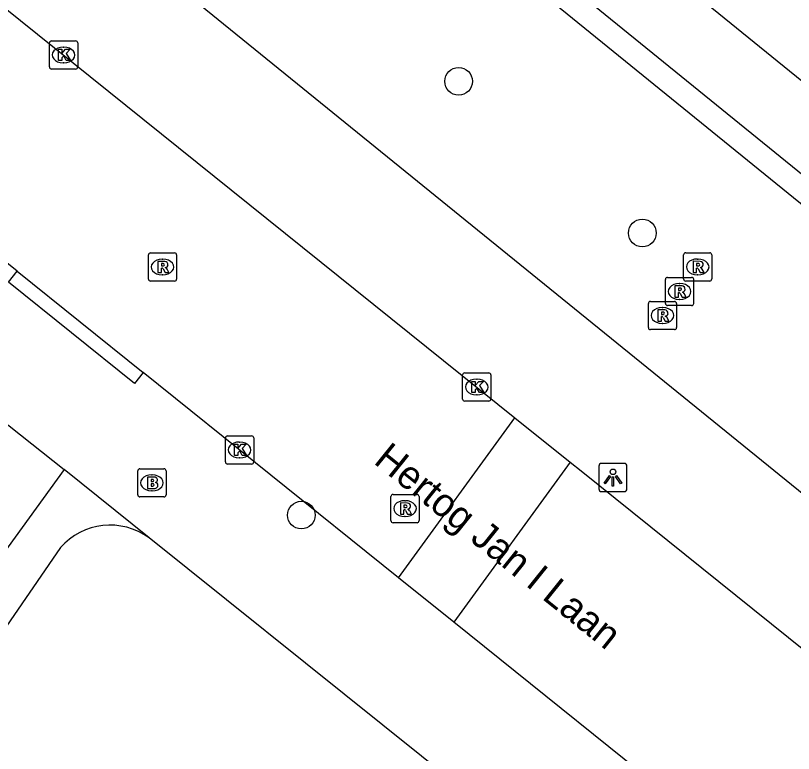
# Model space of a CAD drawing. Extents: x 159675 to 160530, y 382179 to 382901.
# Drawn here: x 160311.53 to 160339.08, y 382679.85 to 382705.99 of the extents above; entities that cross this region are included whole.
import ezdxf

# ---------------------------------------------------------------- set-up
doc = ezdxf.new("R2010")
doc.units = 0
for name, color, linetype in [('IMGEO_Boom', 7, 'Continuous'), ('IMGEO_Brandkraan', 7, 'Continuous'), ('IMGEO_Haag', 7, 'Continuous'), ('IMGEO_Kolk', 7, 'Continuous'), ('IMGEO_Lichtpunt', 7, 'Continuous'), ('IMGEO_Openbare_ruimte_label', 7, 'Continuous'), ('IMGEO_Pand', 7, 'Continuous'), ('IMGEO_Rijbaan_lokaal_open', 7, 'Continuous'), ('IMGEO_Rioolput', 7, 'Continuous'), ('IMGEO_Voetpad_open', 7, 'Continuous')]:
    doc.layers.add(name, color=color, linetype=linetype)

msp = doc.modelspace()

# ---------------------------------------------------------------- linework, layer by layer
at = {"layer": 'IMGEO_Boom'}
for centre in [(160327.217, 382703.665), (160333.725, 382698.29), (160321.648, 382688.295)]:
    msp.add_circle(centre, 0.489, dxfattribs=at)
at = {"layer": 'IMGEO_Brandkraan'}
for p, q in [((160315.853, 382689.013), (160315.853, 382689.865)), ((160315.928, 382689.939), (160316.78, 382689.939)), ((160316.341, 382689.719), (160316.366, 382689.719)), ((160316.854, 382689.865), (160316.854, 382689.013)), ((160316.78, 382688.939), (160315.928, 382688.939)), ((160316.364, 382689.159), (160316.339, 382689.159))]:
    msp.add_line(p, q, dxfattribs=at)
for points in [[(160315.853, 382689.013), (160315.853, 382689.865)], [(160315.928, 382689.939), (160316.78, 382689.939)], [(160316.854, 382689.865), (160316.854, 382689.013)], [(160316.201, 382689.639), (160316.201, 382689.239), (160316.414, 382689.239)], [(160316.432, 382689.639), (160316.201, 382689.639)], [(160316.38, 382689.558), (160316.326, 382689.558), (160316.326, 382689.482)], [(160316.326, 382689.482), (160316.379, 382689.482)], [(160316.388, 382689.406), (160316.326, 382689.406), (160316.326, 382689.325)], [(160316.326, 382689.325), (160316.388, 382689.325)], [(160316.78, 382688.939), (160315.928, 382688.939)]]:
    msp.add_lwpolyline(points, dxfattribs=at)
for centre, radius, start, end in [((160315.93, 382689.863), 0.0765, 91.552, 178.448), ((160315.93, 382689.863), 0.0765, 91.552, 178.448), ((160316.778, 382689.863), 0.0765, 1.552, 88.448), ((160316.778, 382689.863), 0.0765, 1.552, 88.448), ((160316.381, 382689.52), 0.0379, 267.8285, 90.9355), ((160316.436, 382689.494), 0.145, 59.4692, 91.5367), ((160316.461, 382689.541), 0.0922, 285.5137, 58.1501), ((160316.466, 382689.349), 0.105, 301.3115, 78.989), ((160316.389, 382689.365), 0.0404, 269.8759, 90.5077), ((160316.42, 382689.49), 0.251, 268.6676, 293.5347), ((160315.93, 382689.015), 0.0765, 181.552, 268.448), ((160315.93, 382689.015), 0.0765, 181.552, 268.448), ((160316.778, 382689.015), 0.0765, 271.552, 358.448), ((160316.778, 382689.015), 0.0765, 271.552, 358.448)]:
    msp.add_arc(centre, radius, start, end, dxfattribs=at)
for centre, major_axis, ratio, start_param, end_param in [((160316.34, 382689.439), (-0.387, 0.002), 0.722429, 4.712389, 7.853982), ((160316.365, 382689.439), (-0.39, 0.002), 0.717154, 1.570796, 4.712389)]:
    msp.add_ellipse(centre, major_axis=major_axis, ratio=ratio, start_param=start_param, end_param=end_param, dxfattribs=at)
at = {"layer": 'IMGEO_Haag'}
msp.add_lwpolyline([(160362, 382680.937), (160317.229, 382717.291), (160317.757, 382717.941)], dxfattribs=at)
at = {"layer": 'IMGEO_Kolk'}
for p, q in [((160312.724, 382704.172), (160312.724, 382705.024)), ((160312.799, 382705.098), (160313.651, 382705.098)), ((160313.212, 382704.878), (160313.237, 382704.878)), ((160313.725, 382705.024), (160313.725, 382704.172)), ((160313.651, 382704.098), (160312.799, 382704.098)), ((160313.235, 382704.318), (160313.21, 382704.318)), ((160327.436, 382693.334), (160328.288, 382693.334)), ((160327.361, 382692.408), (160327.361, 382693.26)), ((160327.849, 382693.114), (160327.874, 382693.114)), ((160328.362, 382693.26), (160328.362, 382692.408)), ((160327.872, 382692.554), (160327.847, 382692.554)), ((160328.288, 382692.334), (160327.436, 382692.334)), ((160319.034, 382691.104), (160319.886, 382691.104)), ((160318.959, 382690.178), (160318.959, 382691.03)), ((160319.447, 382690.884), (160319.472, 382690.884)), ((160319.96, 382691.03), (160319.96, 382690.178)), ((160319.47, 382690.324), (160319.445, 382690.324)), ((160319.886, 382690.104), (160319.034, 382690.104))]:
    msp.add_line(p, q, dxfattribs=at)
for points in [[(160312.724, 382704.172), (160312.724, 382705.024)], [(160312.799, 382705.098), (160313.651, 382705.098)], [(160313.725, 382705.024), (160313.725, 382704.172)], [(160313.045, 382704.798), (160313.168, 382704.798), (160313.168, 382704.647), (160313.298, 382704.798), (160313.462, 382704.798), (160313.316, 382704.647), (160313.469, 382704.398), (160313.317, 382704.398), (160313.232, 382704.562), (160313.168, 382704.495), (160313.168, 382704.398), (160313.045, 382704.398), (160313.045, 382704.798)], [(160313.651, 382704.098), (160312.799, 382704.098)], [(160327.436, 382693.334), (160328.288, 382693.334)], [(160327.361, 382692.408), (160327.361, 382693.26)], [(160327.682, 382693.034), (160327.805, 382693.034), (160327.805, 382692.883), (160327.935, 382693.034), (160328.099, 382693.034), (160327.953, 382692.883), (160328.106, 382692.634), (160327.954, 382692.634), (160327.869, 382692.798), (160327.805, 382692.731), (160327.805, 382692.634), (160327.682, 382692.634), (160327.682, 382693.034)], [(160328.362, 382693.26), (160328.362, 382692.408)], [(160328.288, 382692.334), (160327.436, 382692.334)], [(160319.034, 382691.104), (160319.886, 382691.104)], [(160318.959, 382690.178), (160318.959, 382691.03)], [(160319.96, 382691.03), (160319.96, 382690.178)], [(160319.28, 382690.804), (160319.403, 382690.804), (160319.403, 382690.653), (160319.533, 382690.804), (160319.697, 382690.804), (160319.551, 382690.653), (160319.704, 382690.404), (160319.552, 382690.404), (160319.467, 382690.568), (160319.403, 382690.501), (160319.403, 382690.404), (160319.28, 382690.404), (160319.28, 382690.804)], [(160319.886, 382690.104), (160319.034, 382690.104)]]:
    msp.add_lwpolyline(points, dxfattribs=at)
for centre, start, end in [((160312.801, 382705.022), 91.552, 178.448), ((160312.801, 382705.022), 91.552, 178.448), ((160313.649, 382705.022), 1.552, 88.448), ((160313.649, 382705.022), 1.552, 88.448), ((160312.801, 382704.174), 181.552, 268.448), ((160312.801, 382704.174), 181.552, 268.448), ((160313.649, 382704.174), 271.552, 358.448), ((160313.649, 382704.174), 271.552, 358.448), ((160327.438, 382693.258), 91.552, 178.448), ((160327.438, 382693.258), 91.552, 178.448), ((160328.286, 382693.258), 1.552, 88.448), ((160328.286, 382693.258), 1.552, 88.448), ((160327.438, 382692.41), 181.552, 268.448), ((160327.438, 382692.41), 181.552, 268.448), ((160328.286, 382692.41), 271.552, 358.448), ((160328.286, 382692.41), 271.552, 358.448), ((160319.036, 382691.028), 91.552, 178.448), ((160319.036, 382691.028), 91.552, 178.448), ((160319.884, 382691.028), 1.552, 88.448), ((160319.884, 382691.028), 1.552, 88.448), ((160319.036, 382690.18), 181.552, 268.448), ((160319.036, 382690.18), 181.552, 268.448), ((160319.884, 382690.18), 271.552, 358.448), ((160319.884, 382690.18), 271.552, 358.448)]:
    msp.add_arc(centre, 0.0765, start, end, dxfattribs=at)
for centre, major_axis, ratio, start_param, end_param in [((160313.211, 382704.598), (-0.387, 0.002), 0.722429, 4.712389, 7.853982), ((160313.236, 382704.598), (-0.39, 0.002), 0.717154, 1.570796, 4.712389), ((160327.848, 382692.834), (-0.387, 0.002), 0.722429, 4.712389, 7.853982), ((160327.873, 382692.834), (-0.39, 0.002), 0.717154, 1.570796, 4.712389), ((160319.446, 382690.604), (-0.387, 0.002), 0.722429, 4.712389, 7.853982), ((160319.471, 382690.604), (-0.39, 0.002), 0.717154, 1.570796, 4.712389)]:
    msp.add_ellipse(centre, major_axis=major_axis, ratio=ratio, start_param=start_param, end_param=end_param, dxfattribs=at)
at = {"layer": 'IMGEO_Lichtpunt'}
for p, q in [((160332.186, 382690.031), (160332.186, 382689.224)), ((160332.186, 382690.031), (160332.186, 382689.224)), ((160333.088, 382690.126), (160332.28, 382690.126)), ((160333.088, 382690.126), (160332.28, 382690.126)), ((160333.182, 382689.224), (160333.182, 382690.031)), ((160333.182, 382689.224), (160333.182, 382690.031)), ((160332.28, 382689.13), (160333.088, 382689.13)), ((160332.28, 382689.13), (160333.088, 382689.13))]:
    msp.add_line(p, q, dxfattribs=at)
for points in [[(160332.56, 382689.695), (160332.599, 382689.667), (160332.411, 382689.405), (160332.373, 382689.432), (160332.56, 382689.695)], [(160332.662, 382689.647), (160332.709, 382689.647), (160332.709, 382689.325), (160332.662, 382689.325), (160332.662, 382689.647)], [(160332.772, 382689.667), (160332.81, 382689.694), (160332.997, 382689.432), (160332.958, 382689.404), (160332.772, 382689.667)]]:
    msp.add_lwpolyline(points, dxfattribs=at)
msp.add_circle((160332.685, 382689.829), 0.0994, dxfattribs=at)
for centre, start, end in [((160332.28, 382690.031), 90, 180), ((160332.28, 382690.031), 90, 180), ((160333.088, 382690.031), 0, 90), ((160333.088, 382690.031), 0, 90), ((160332.28, 382689.224), 180, 270), ((160332.28, 382689.224), 180, 270), ((160333.088, 382689.224), 270, 0), ((160333.088, 382689.224), 270, 360)]:
    msp.add_arc(centre, 0.0946, start, end, dxfattribs=at)
at = {"layer": 'IMGEO_Pand'}
msp.add_lwpolyline([(160360.202, 382686.777), (160373.514, 382703.17), (160373.99, 382702.783), (160379.13, 382709.111), (160381.203, 382707.428), (160385.383, 382712.576), (160383.354, 382714.223), (160388.465, 382720.517), (160387.964, 382720.924), (160401.236, 382737.269), (160363.137, 382768.208), (160322.118, 382717.701), (160360.202, 382686.777)], dxfattribs=at)
at = {"layer": 'IMGEO_Rijbaan_lokaal_open'}
for points in [[(160292.249, 382721.456), (160329.213, 382691.747)], [(160311.584, 382696.94), (160287.892, 382716)], [(160311.584, 382696.94), (160316.045, 382693.352)], [(160325.09, 382686.076), (160316.045, 382693.352)], [(160309.343, 382693.001), (160313.249, 382689.912)], [(160325.09, 382686.076), (160329.213, 382691.747)], [(160329.213, 382691.747), (160331.172, 382690.173)], [(160331.172, 382690.173), (160327.048, 382684.5)], [(160331.172, 382690.173), (160331.562, 382689.859), (160344.376, 382679.555)], [(160313.249, 382689.912), (160284.25, 382649.875)], [(160327.048, 382684.5), (160325.09, 382686.076)], [(160335.801, 382677.459), (160327.048, 382684.5)]]:
    msp.add_lwpolyline(points, dxfattribs=at)
at = {"layer": 'IMGEO_Rioolput'}
for p, q in [((160316.229, 382696.66), (160316.229, 382697.512)), ((160316.304, 382697.586), (160317.156, 382697.586)), ((160317.23, 382697.512), (160317.23, 382696.66)), ((160335.186, 382696.662), (160335.186, 382697.514)), ((160335.261, 382697.588), (160336.113, 382697.588)), ((160336.187, 382697.514), (160336.187, 382696.662)), ((160316.717, 382697.366), (160316.742, 382697.366)), ((160335.674, 382697.368), (160335.699, 382697.368)), ((160316.74, 382696.806), (160316.715, 382696.806)), ((160334.543, 382695.793), (160334.543, 382696.645)), ((160334.618, 382696.719), (160335.47, 382696.719)), ((160335.544, 382696.645), (160335.544, 382695.793)), ((160335.697, 382696.808), (160335.672, 382696.808)), ((160317.156, 382696.586), (160316.304, 382696.586)), ((160335.031, 382696.499), (160335.056, 382696.499)), ((160336.113, 382696.588), (160335.261, 382696.588)), ((160333.939, 382694.941), (160333.939, 382695.793)), ((160334.014, 382695.867), (160334.866, 382695.867)), ((160334.94, 382695.793), (160334.94, 382694.941)), ((160335.054, 382695.939), (160335.029, 382695.939)), ((160334.427, 382695.647), (160334.452, 382695.647)), ((160335.47, 382695.719), (160334.618, 382695.719)), ((160334.45, 382695.087), (160334.425, 382695.087)), ((160334.866, 382694.867), (160334.014, 382694.867)), ((160324.82, 382688.1), (160324.82, 382688.952)), ((160324.895, 382689.026), (160325.747, 382689.026)), ((160325.821, 382688.952), (160325.821, 382688.1)), ((160325.308, 382688.806), (160325.333, 382688.806)), ((160325.331, 382688.246), (160325.306, 382688.246)), ((160325.747, 382688.026), (160324.895, 382688.026))]:
    msp.add_line(p, q, dxfattribs=at)
for points in [[(160316.229, 382696.66), (160316.229, 382697.512)], [(160316.304, 382697.586), (160317.156, 382697.586)], [(160317.23, 382697.512), (160317.23, 382696.66)], [(160335.186, 382696.662), (160335.186, 382697.514)], [(160335.261, 382697.588), (160336.113, 382697.588)], [(160336.187, 382697.514), (160336.187, 382696.662)], [(160316.818, 382697.284), (160316.566, 382697.286), (160316.566, 382696.886)], [(160316.744, 382697.205), (160316.69, 382697.205), (160316.69, 382697.124)], [(160335.775, 382697.286), (160335.523, 382697.288), (160335.523, 382696.888)], [(160335.701, 382697.207), (160335.647, 382697.207), (160335.647, 382697.126)], [(160316.566, 382696.886), (160316.69, 382696.886), (160316.69, 382697.048), (160316.701, 382697.048)], [(160316.69, 382697.124), (160316.742, 382697.124)], [(160316.748, 382697.019), (160316.819, 382696.886), (160316.959, 382696.886), (160316.894, 382697.012)], [(160335.523, 382696.888), (160335.647, 382696.888), (160335.647, 382697.05), (160335.658, 382697.05)], [(160335.647, 382697.126), (160335.699, 382697.126)], [(160335.705, 382697.021), (160335.776, 382696.888), (160335.916, 382696.888), (160335.851, 382697.014)], [(160334.543, 382695.793), (160334.543, 382696.645)], [(160334.618, 382696.719), (160335.47, 382696.719)], [(160335.544, 382696.645), (160335.544, 382695.793)], [(160317.156, 382696.586), (160316.304, 382696.586)], [(160335.132, 382696.417), (160334.88, 382696.419), (160334.88, 382696.019)], [(160335.058, 382696.338), (160335.004, 382696.338), (160335.004, 382696.257)], [(160336.113, 382696.588), (160335.261, 382696.588)], [(160334.88, 382696.019), (160335.004, 382696.019), (160335.004, 382696.181), (160335.015, 382696.181)], [(160335.004, 382696.257), (160335.056, 382696.257)], [(160335.062, 382696.152), (160335.133, 382696.019), (160335.273, 382696.019), (160335.208, 382696.145)], [(160333.939, 382694.941), (160333.939, 382695.793)], [(160334.014, 382695.867), (160334.866, 382695.867)], [(160334.94, 382695.793), (160334.94, 382694.941)], [(160334.528, 382695.565), (160334.276, 382695.567), (160334.276, 382695.167)], [(160335.47, 382695.719), (160334.618, 382695.719)], [(160334.276, 382695.167), (160334.4, 382695.167), (160334.4, 382695.329), (160334.411, 382695.329)], [(160334.454, 382695.486), (160334.4, 382695.486), (160334.4, 382695.405)], [(160334.4, 382695.405), (160334.452, 382695.405)], [(160334.458, 382695.3), (160334.529, 382695.167), (160334.669, 382695.167), (160334.604, 382695.293)], [(160334.866, 382694.867), (160334.014, 382694.867)], [(160324.82, 382688.1), (160324.82, 382688.952)], [(160324.895, 382689.026), (160325.747, 382689.026)], [(160325.821, 382688.952), (160325.821, 382688.1)], [(160325.409, 382688.724), (160325.157, 382688.726), (160325.157, 382688.326)], [(160325.335, 382688.645), (160325.281, 382688.645), (160325.281, 382688.564)], [(160325.157, 382688.326), (160325.281, 382688.326), (160325.281, 382688.488), (160325.292, 382688.488)], [(160325.281, 382688.564), (160325.333, 382688.564)], [(160325.339, 382688.459), (160325.41, 382688.326), (160325.55, 382688.326), (160325.485, 382688.452)], [(160325.747, 382688.026), (160324.895, 382688.026)]]:
    msp.add_lwpolyline(points, dxfattribs=at)
for centre, radius, start, end in [((160316.306, 382697.51), 0.0765, 91.552, 178.448), ((160316.306, 382697.51), 0.0765, 91.552, 178.448), ((160317.154, 382697.51), 0.0765, 1.552, 88.448), ((160317.154, 382697.51), 0.0765, 1.552, 88.448), ((160335.263, 382697.512), 0.0765, 91.552, 178.448), ((160335.263, 382697.512), 0.0765, 91.552, 178.448), ((160336.111, 382697.512), 0.0765, 1.552, 88.448), ((160336.111, 382697.512), 0.0765, 1.552, 88.448), ((160316.75, 382697.109), 0.0964, 77.0061, 93.1865), ((160316.764, 382697.166), 0.0378, 276.6634, 79.6772), ((160316.817, 382697.174), 0.109, 350.3612, 89.416), ((160316.815, 382697.174), 0.112, 277.5842, 350.9817), ((160335.707, 382697.111), 0.0964, 77.0061, 93.1865), ((160335.721, 382697.168), 0.0378, 276.6634, 79.6772), ((160335.774, 382697.176), 0.109, 350.3612, 89.416), ((160335.772, 382697.176), 0.112, 277.5842, 350.9817), ((160316.7, 382696.995), 0.0533, 26.0293, 88.6989), ((160316.726, 382697.313), 0.19, 274.7715, 282.9687), ((160316.799, 382696.959), 0.108, 29.5134, 73.7905), ((160335.657, 382696.997), 0.0533, 26.0293, 88.6989), ((160335.683, 382697.315), 0.19, 274.7715, 282.9687), ((160335.756, 382696.961), 0.108, 29.5134, 73.7905), ((160316.306, 382696.662), 0.0765, 181.552, 268.448), ((160316.306, 382696.662), 0.0765, 181.552, 268.448), ((160317.154, 382696.662), 0.0765, 271.552, 358.448), ((160317.154, 382696.662), 0.0765, 271.552, 358.448), ((160334.62, 382696.643), 0.0765, 91.552, 178.448), ((160334.62, 382696.643), 0.0765, 91.552, 178.448), ((160335.263, 382696.664), 0.0765, 181.552, 268.448), ((160335.263, 382696.664), 0.0765, 181.552, 268.448), ((160335.468, 382696.643), 0.0765, 1.552, 88.448), ((160335.468, 382696.643), 0.0765, 1.552, 88.448), ((160336.111, 382696.664), 0.0765, 271.552, 358.448), ((160336.111, 382696.664), 0.0765, 271.552, 358.448), ((160335.064, 382696.242), 0.0964, 77.0061, 93.1865), ((160335.078, 382696.299), 0.0378, 276.6634, 79.6772), ((160335.131, 382696.307), 0.109, 350.3612, 89.416), ((160335.014, 382696.128), 0.0533, 26.0293, 88.6989), ((160335.04, 382696.446), 0.19, 274.7715, 282.9687), ((160335.129, 382696.307), 0.112, 277.5842, 350.9817), ((160335.113, 382696.092), 0.108, 29.5134, 73.7905), ((160334.016, 382695.791), 0.0765, 91.552, 178.448), ((160334.016, 382695.791), 0.0765, 91.552, 178.448), ((160334.62, 382695.795), 0.0765, 181.552, 268.448), ((160334.62, 382695.795), 0.0765, 181.552, 268.448), ((160334.864, 382695.791), 0.0765, 1.552, 88.448), ((160334.864, 382695.791), 0.0765, 1.552, 88.448), ((160335.468, 382695.795), 0.0765, 271.552, 358.448), ((160335.468, 382695.795), 0.0765, 271.552, 358.448), ((160334.527, 382695.455), 0.109, 350.3612, 89.416), ((160334.41, 382695.276), 0.0533, 26.0293, 88.6989), ((160334.436, 382695.594), 0.19, 274.7715, 282.9687), ((160334.46, 382695.39), 0.0964, 77.0061, 93.1865), ((160334.474, 382695.447), 0.0378, 276.6634, 79.6772), ((160334.525, 382695.455), 0.112, 277.5842, 350.9817), ((160334.509, 382695.24), 0.108, 29.5134, 73.7905), ((160334.016, 382694.943), 0.0765, 181.552, 268.448), ((160334.016, 382694.943), 0.0765, 181.552, 268.448), ((160334.864, 382694.943), 0.0765, 271.552, 358.448), ((160334.864, 382694.943), 0.0765, 271.552, 358.448), ((160324.897, 382688.95), 0.0765, 91.552, 178.448), ((160324.897, 382688.95), 0.0765, 91.552, 178.448), ((160325.745, 382688.95), 0.0765, 1.552, 88.448), ((160325.745, 382688.95), 0.0765, 1.552, 88.448), ((160325.341, 382688.549), 0.0964, 77.0061, 93.1865), ((160325.355, 382688.606), 0.0378, 276.6634, 79.6772), ((160325.408, 382688.614), 0.109, 350.3612, 89.416), ((160325.291, 382688.435), 0.0533, 26.0293, 88.6989), ((160325.317, 382688.753), 0.19, 274.7715, 282.9687), ((160325.406, 382688.614), 0.112, 277.5842, 350.9817), ((160325.39, 382688.399), 0.108, 29.5134, 73.7905), ((160324.897, 382688.102), 0.0765, 181.552, 268.448), ((160324.897, 382688.102), 0.0765, 181.552, 268.448), ((160325.745, 382688.102), 0.0765, 271.552, 358.448), ((160325.745, 382688.102), 0.0765, 271.552, 358.448)]:
    msp.add_arc(centre, radius, start, end, dxfattribs=at)
for centre, major_axis, ratio, start_param, end_param in [((160316.716, 382697.086), (-0.387, 0.002), 0.722429, 4.712389, 7.853982), ((160316.741, 382697.086), (-0.39, 0.002), 0.717154, 1.570796, 4.712389), ((160335.673, 382697.088), (-0.387, 0.002), 0.722429, 4.712389, 7.853982), ((160335.698, 382697.088), (-0.39, 0.002), 0.717154, 1.570796, 4.712389), ((160335.03, 382696.219), (-0.387, 0.002), 0.722429, 4.712389, 7.853982), ((160335.055, 382696.219), (-0.39, 0.002), 0.717154, 1.570796, 4.712389), ((160334.426, 382695.367), (-0.387, 0.002), 0.722429, 4.712389, 7.853982), ((160334.451, 382695.367), (-0.39, 0.002), 0.717154, 1.570796, 4.712389), ((160325.307, 382688.526), (-0.387, 0.002), 0.722429, 4.712389, 7.853982), ((160325.332, 382688.526), (-0.39, 0.002), 0.717154, 1.570796, 4.712389)]:
    msp.add_ellipse(centre, major_axis=major_axis, ratio=ratio, start_param=start_param, end_param=end_param, dxfattribs=at)
at = {"layer": 'IMGEO_Voetpad_open'}
for points in [[(160357.009, 382674.758), (160346.941, 382682.927), (160284.89, 382733.272)], [(160317.757, 382717.941), (160360.708, 382683.056), (160375.385, 382701.033), (160376.864, 382699.817)], [(160316.045, 382693.352), (160315.733, 382692.962), (160311.272, 382696.55), (160311.584, 382696.94)], [(160316.257, 382687.487), (160313.249, 382689.912)], [(160332.815, 382674.214), (160316.257, 382687.487)], [(160313.115, 382687.143), (160310.913, 382683.952), (160308.167, 382680.148)]]:
    msp.add_lwpolyline(points, dxfattribs=at)
msp.add_arc((160314.874, 382685.601), 2.339, 53.7429, 138.7534, dxfattribs=at)

# ---------------------------------------------------------------- texts
at = {"layer": 'IMGEO_Openbare_ruimte_label'}
msp.add_text('Hertog Jan I Laan', height=1, rotation=321.1702, dxfattribs=at).set_placement((160324.172, 382690.154))

doc.saveas('drawing.dxf')
